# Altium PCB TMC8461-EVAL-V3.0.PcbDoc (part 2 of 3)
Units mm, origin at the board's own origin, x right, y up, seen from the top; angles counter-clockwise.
Board outline 79 x 85 mm, 4 copper layers (Top Layer, Mid1, Mid2, Bottom Layer), stack 1.572 mm thick; 182 components, 192 nets, 883 pads, 381 vias.
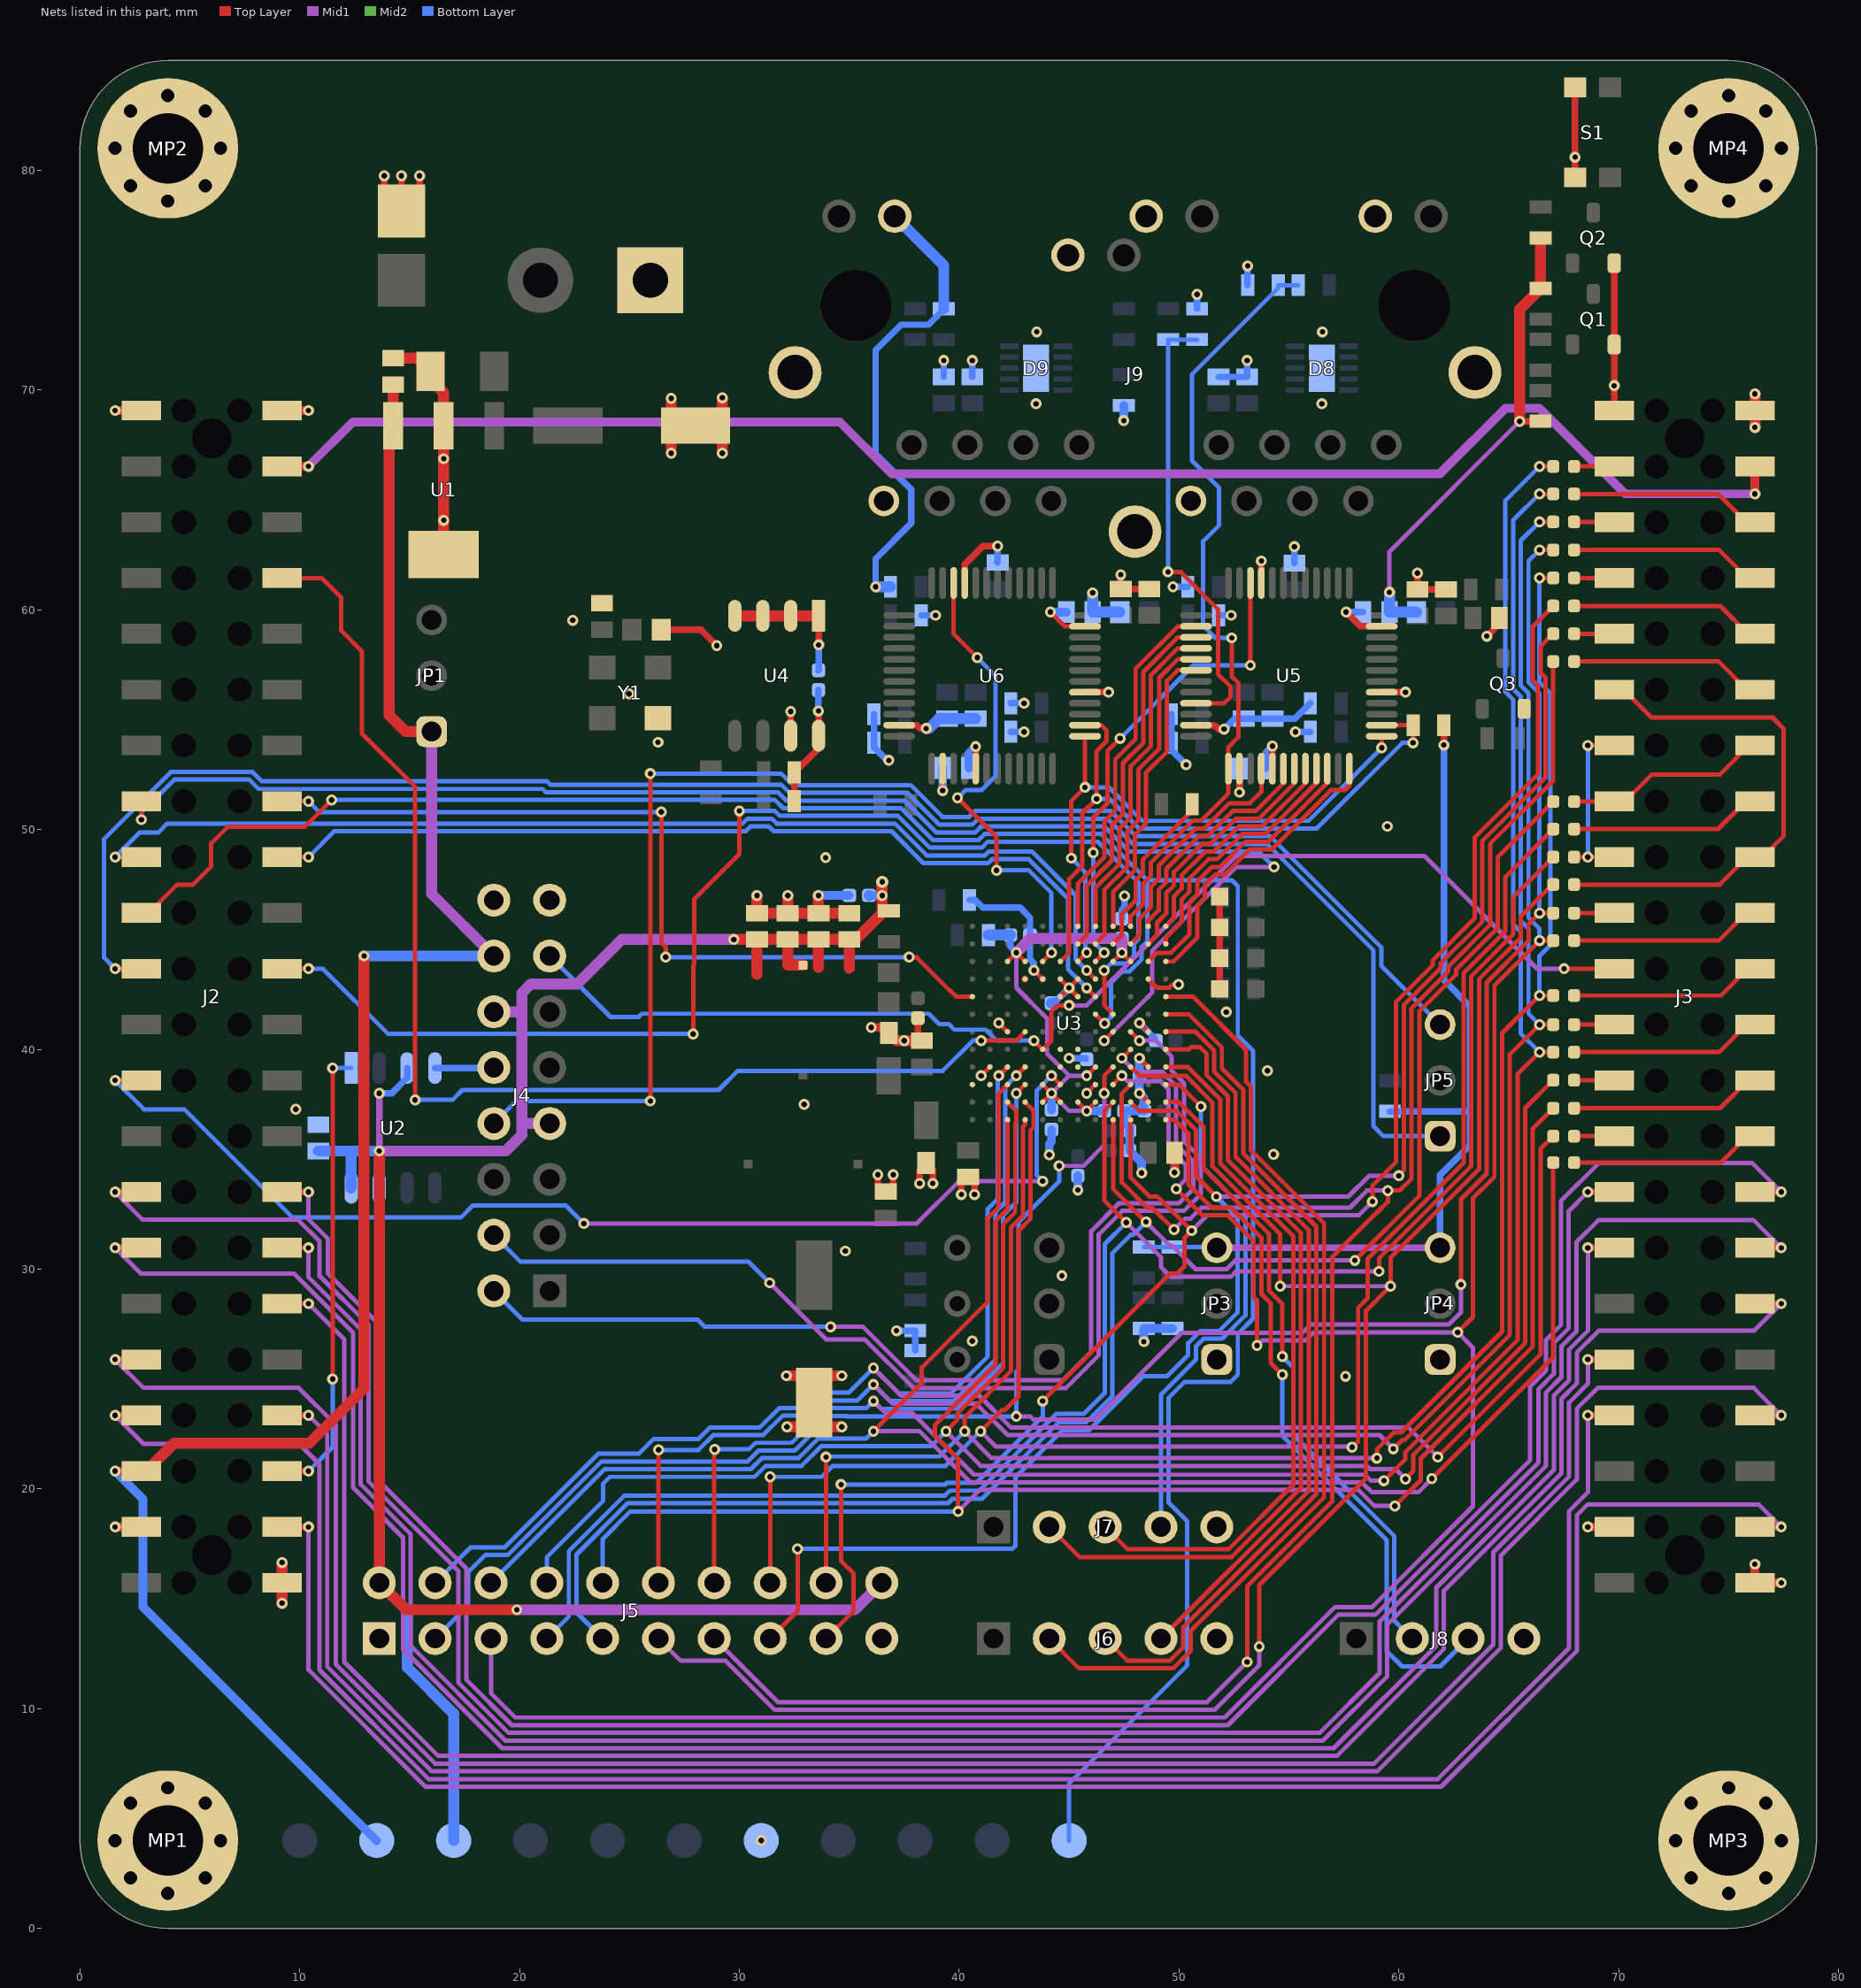
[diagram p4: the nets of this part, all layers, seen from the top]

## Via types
v1: diameter 0.5, hole 0.25, Top Layer to Bottom Layer, tented both sides, 379 vias
v2: diameter 0.5/0.5/0.5/0.5 (per signal layer), hole 0.25, Top Layer to Bottom Layer, tented both sides, 1 vias
v3: diameter 0.55, hole 0.25, Top Layer to Bottom Layer, tented both sides, 1 vias

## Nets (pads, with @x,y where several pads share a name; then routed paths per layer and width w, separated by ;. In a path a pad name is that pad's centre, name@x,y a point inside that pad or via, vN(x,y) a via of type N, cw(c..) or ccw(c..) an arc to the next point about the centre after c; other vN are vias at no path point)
+3V3: C4.2 C8.2 C9.2 C10.2 C11.2 C12.2 C24.2 C25.2 C26.2 C27.2 C30.2 C31.2 C32.2 C40.2 C41.2 J4.7 J4.12 J5.2 J5.20 J9.B11 JP3.3 JP4.3 L2.2 L4.2 L5.1 L6.1 R22.1 R28.2 R30.1 R32.2 R33.2 R40.2 R41.2 R44.2 R45.2 R46.2 R47.2 R49.1 R56.2 R60.1 R63.2 R67.2 TP3.1 U2.3 U2.7 U2.8 U3.C3 U3.D3 U3.E9 U3.E11 U3.F11 U3.G11 U3.H10 U3.H11 U3.J3 U3.K3 U4.8 U5.14 U6.14 | length 238.6
  Top Layer w0.2: v1(39.25,51.775) U6.14@39.25,52.775 ; U3.K3@42.2,44 v1(42.6,44.4) U3.J3@43,44 ; U3.H11@43.8,37.6 v1(44.2,38) ; U3.H10@43.8,38.4 v1(44.2,38) ; U3.G11@44.6,37.6 v1(44.2,38) ; U3.F11@45.4,37.6 v1(45.8,37.2) U3.E11@46.2,37.6 ; v1(45.8,38.8) U3.E9@46.2,39.2 ; U3.D3@47,44 v1(47.4,44.4) U3.C3@47.8,44
  Top Layer w0.3: L4.2@26.44,59.1 28.25,59.1 v1(28.975,58.375) ; R46.2@32.5,51.3 R45.2@32.5,52.6 33.605,53.705 U4.8@33.605,54.275 v1@33.605,55.4 ; v1@52.75,51.65 U5.14@52.75,52.775 ; v1(62.05,53.85) R44.2@62.05,54.75 ; v1@65.505,68.58 R30.1@66.445,68.58
  Top Layer w0.5: v1(13.62,35.375) J5.2@13.62,15.73 14.85,14.5 v1(19.875,14.5) ; v1(29.75,45) C11.2@30.8,45 ; 30.8,43.405 C11.2@30.8,45 ; L2.2@32.899,43.833 32.2,43.833 C10.2@32.2,45 ; 33.6,43.73 C9.2@33.6,45 ; 35,43.7 C8.2@35,45 ; v3(36.5,47.625) v1(36.5,47) 36.5,46.4 R22.1@36.6,46.3 ; R22.1@36.8,46.3 R22.1@36.6,46.3 ; v1(65.5,68.575) 65.5,73.675 R32.2@66.45,74.625 R33.2@66.45,76.925 ; C11.2@30.8,45 C10.2@32.2,45 ; C10.2@32.2,45 C9.2@33.6,45 ; C9.2@33.6,45 C8.2@35,45 ; C8.2@35,45 35.3,45 R22.1@36.6,46.3
  Mid1 w0.2: v1(42.6,44.4) 42.6,42.8 44,41.4 44,39.8 45,38.8 ; v1(45.8,37.2) 45,37.2 v1(44.2,38) 45,38.8 ; v1(45.8,38.8) 45,38.8 ; v1(59.575,60.8) 59.575,62.65 v1(65.5,68.575)
  Mid1 w0.3: v1(13.62,35.375) v1(13.62,38) ; JP3.3@51.72,30.97 JP4.3@61.88,30.97
  Mid1 w0.5: v1(13.62,35.375) 19.375,35.375 20.1,36.1 20.1,36.63 ; J4.12@18.83,41.71 20.06,41.71 ; v1(19.875,14.5) 35.25,14.5 J5.20@36.48,15.73 ; J4.7@21.37,36.63 20.1,36.63 ; v1(29.75,45) 24.65,45 22.625,42.975 20.525,42.975 20.1,42.55 20.1,36.63 ; v1(42.6,44.4) 43.25,45.05 47.4,45.05 v1(47.4,44.4)
  Mid2 w0.5: v1(36.5,47) v3(36.5,47.625)
  Bottom Layer w0.2: v1(47.4,44.4) C24.2@47.4,45.15 ; R41.2@48.4,31 R40.2@49.7,31 51.69,31 JP3.3@51.72,30.97
  Bottom Layer w0.3: v1(13.62,38) 14.187,38 14.885,38.698 U2.3@14.885,39.15 ; v1(33.6,55.4) C30.2@33.6,56.35 ; v1(36.2,61.05) 36.2,62.325 37.825,63.95 37.825,65.475 36.2,67.1 36.2,71.825 37.35,72.975 38.6,72.975 39.3,73.675 R63.2@39.3,73.7 ; C27.2@42.325,45.2 42.325,44.675 v1(42.6,44.4) ; R60.1@42.35,54.45 v1(42.95,54.45) ; v1(49.725,61.05) R56.2@50.4,61.05 ; v1(52.75,51.7) C31.2@52.75,52.775 ; v1(55.3,54.45) R49.1@55.975,54.45 ; R47.2@59.6,37.18 63.205,37.18 63.25,37.225 ; JP4.3@61.88,30.97 61.88,34.28 63.25,35.65 63.25,37.225 ; v1(62.05,53.85) 62.05,43.15 63.25,41.95 63.25,37.225
  Bottom Layer w0.4: C12.2@35.905,47 v1(36.5,47) ; v1(39.25,51.775) C40.2@39.25,52.8 ; C26.2@44.2,37.25 v1(44.2,38) ; v1(45.8,37.2) C25.2@46.6,37.2
  Bottom Layer w0.5: C4.2@10.85,35.375 12.35,35.375 ; U2.8@12.345,33.7 12.345,35.37 12.35,35.375 ; U2.7@13.615,33.7 13.62,33.705 v1(13.62,35.375) 12.35,35.375 ; J5.2@13.62,15.73 14.9,14.45 14.9,11.875 17,9.775 TP3.1@17,4 ; C12.2@35.9,47.005 C12.2@35.905,47 ; v1(36.2,61.05) R67.2@36.875,61.05 ; J9.B11@37.07,77.91 39.3,75.68 R63.2@39.3,73.7 ; R28.2@41.325,45.2 C27.2@42.325,45.2 ; v1(46.075,60.775) C41.2@46.075,59.9 L6.1@47.31,59.9 ; v1(59.575,60.8) C32.2@59.575,59.9 L5.1@60.81,59.9
+5V_REG: C3.2 J2.5 J4.14 JP1.1 TP2.1 U1.3 | length 88.9
  Top Layer w0.4: v1(1.6,20.81) J2.5@2.8,20.81
  Top Layer w0.5: J2.5@2.8,20.81 3.01,20.81 4.275,22.075 10.425,22.075 12.925,24.575 v1(12.925,44.25) ; C3.2@14.25,70.25 U1.3@14.25,68.375 14.075,68.2 14.075,55.2 14.815,54.46 JP1.1@16,54.46
  Mid1 w0.5: JP1.1@16,54.46 16,47.08 J4.14@18.83,44.25
  Bottom Layer w0.4: v1(1.6,20.81) 2.875,19.535 2.875,14.625 TP2.1@13.5,4
  Bottom Layer w0.5: v1(12.925,44.25) J4.14@18.83,44.25
+5V_VM: J2.42 J3.42 | length 72.9
  Top Layer w0.4: J2.42@9.2,66.53 v1(10.4,66.53) ; v1(76.2,65.275) J3.42@76.2,66.53
  Mid1 w0.4: v1(10.4,66.53) 12.42,68.55 34.575,68.55 36.925,66.2 61.875,66.2 64.85,69.175 66.4,69.175 70.3,65.275 v1(76.2,65.275)
\S\P\I\1\_\C\S\: J2.30 U3.M5 | length 38.8
  Top Layer w0.2: J2.30@9.2,51.29 v1(10.4,51.29) ; v1(26.45,50.8) 26.45,44.85 26.65,44.65 v1(26.65,44.2) ; v1(37.725,44.2) 38.073,44.2 38.083,44.19 38.083,44.167 39.594,42.657 39.616,42.657 39.873,42.4 U3.M5@40.6,42.4
  Bottom Layer w0.2: v1(10.4,51.29) 10.89,50.8 v1(26.45,50.8) ; v1(26.65,44.2) v1(37.725,44.2)
AIN0: J2.14 J3.14 | length 103.4
  Top Layer w0.2: J2.14@9.2,30.97 v1(10.4,30.97)
  Top Layer w0.3: J3.14@76.2,30.97 v1(77.4,30.97)
  Mid1 w0.2: v1(10.4,30.97) 10.4,29.632 12.775,27.257 12.775,20.205 15.05,17.93 15.05,12.855 19.355,8.55 56.55,8.55 59.475,11.475 59.475,13.825 66.7,21.05 66.7,24.39 67.4,25.09 67.4,26.49 68.075,27.165 68.075,31.225 69.075,32.225 76.145,32.225 v1(77.4,30.97)
AIN1: J2.15 J3.15 | length 105.1
  Top Layer w0.3: v1(1.6,33.51) J2.15@2.8,33.51 ; v1(68.6,33.51) J3.15@69.8,33.51
  Mid1 w0.2: v1(1.6,33.51) 2.86,32.25 9.925,32.25 10.9,31.275 10.9,29.7 13.125,27.475 13.125,20.35 17.225,16.25 17.225,11.175 19.5,8.9 56.405,8.9 59.125,11.62 59.125,13.97 66.35,21.195 66.35,24.535 67.05,25.235 67.05,26.635 67.725,27.31 67.725,32.635 v1(68.6,33.51)
AIN2: J2.16 J3.16 | length 105.5
  Top Layer w0.3: J2.16@9.2,33.51 v1(10.4,33.51) ; J3.16@76.2,33.51 v1(77.4,33.51)
  Mid1 w0.2: v1(10.4,33.51) 10.4,32.27 11.275,31.395 11.275,29.82 13.475,27.62 13.475,20.495 17.575,16.395 17.575,11.33 19.655,9.25 52.225,9.25 57.25,14.275 58.935,14.275 65.975,21.315 65.975,24.655 66.7,25.38 66.7,26.78 67.375,27.455 67.375,33.1 69.1,34.825 76.085,34.825 v1(77.4,33.51)
CLK_16MHZ_OUT: J3.23 J4.13 U3.H8 | length 56.9
  Top Layer w0.2: v1(43.4,40.4) U3.H8@43.8,40 44.2,40.4 44.2,41.73 44.47,42 v1(45,42) ; v1(67.52,43.67) J3.23@69.8,43.67
  Mid1 w0.2: v1(45,42) 45.8,42 52.6,48.8 61.165,48.8 66.295,43.67 v1(67.52,43.67)
  Bottom Layer w0.2: J4.13@21.37,44.25 24.145,41.475 25.408,41.475 25.558,41.625 38.618,41.625 39.093,41.15 39.525,41.15 39.775,40.9 41.207,40.9 41.5,40.607 41.5,40.6 41.7,40.4 v1(43.4,40.4)
CLK_25MHZ_OUT0: U3.E3 U5.46 | length 22.1
  Top Layer w0.2: v1(46.1,48.95) 46.1,50.55 46.45,50.9 46.457,50.9 46.75,51.193 46.75,53.575 v1(47.325,54.15) ; U3.E3@46.2,44 v1(46.6,44.4) ; v1(53.25,57.475) U5.46@53.25,61.225
  Bottom Layer w0.2: v1(46.1,48.95) 46.1,44.9 v1(46.6,44.4) ; v1(47.325,54.15) 50.65,57.475 v1(53.25,57.475)
CLK_25MHZ_OUT1: U3.H3 U6.46 | length 21.9
  Top Layer w0.2: U6.46@39.75,61.225 39.75,58.9 v1(40.825,57.825) ; v1(39.925,51.45) 41.675,49.7 ; v1(41.7,48.15) 41.7,49.675 ; U3.H3@43.8,44 v1(44.2,44.4)
  Bottom Layer w0.2: v1(39.925,51.45) 39.95,51.45 40.3,51.8 41.025,51.8 41.65,52.425 41.65,57 v1(40.825,57.825) ; v1(41.7,48.15) 43.17,48.15 44.2,47.12 v1(44.2,44.4)
CS_CH0: J2.6 U2.1 | length 20.8
  Top Layer w0.2: v1(11.5,25) v1(11.5,39.15)
  Top Layer w0.3: J2.6@9.2,20.81 v1(10.4,20.81)
  Bottom Layer w0.2: v1(10.4,20.81) 11.5,21.91 v1(11.5,25) ; v1(11.5,39.15) U2.1@12.345,39.15
DIO0: J2.8 J3.8 | length 94.4
  Top Layer w0.3: J2.8@9.2,23.35 v1(10.4,23.35) ; J3.8@76.2,23.35 v1(77.4,23.35)
  Mid1 w0.2: v1(10.4,23.35) 11.25,22.5 11.25,11.91 16.01,7.15 59.019,7.15 64.65,12.781 64.65,16.975 68.1,20.425 68.1,23.65 69.05,24.6 76.15,24.6 v1(77.4,23.35)
DIO1: J2.9 J3.9 | length 96.1
  Top Layer w0.3: v1(1.6,25.89) J2.9@2.8,25.89 ; v1(68.6,25.89) J3.9@69.8,25.89
  Mid1 w0.2: v1(1.6,25.89) 2.89,24.6 9.95,24.6 11.65,22.9 11.65,12.005 16.155,7.5 58.874,7.5 64.3,12.926 64.3,17.12 67.75,20.57 67.75,23.936 68.6,24.786 v1(68.6,25.89)
DIO4: J2.12 J3.12 | length 99.4
  Top Layer w0.2: J2.12@9.2,28.43 v1(10.4,28.43)
  Top Layer w0.3: J3.12@76.2,28.43 v1(77.4,28.43)
  Mid1 w0.2: v1(10.4,28.43) 12.025,26.805 12.025,12.125 16.3,7.85 57.179,7.85 62.05,12.721 62.05,15.365 67.4,20.715 67.4,24.1 68.1,24.8 68.1,26.2 69.1,27.2 76.17,27.2 v1(77.4,28.43)
DIO5: J2.13 J3.13 | length 101.9
  Top Layer w0.3: v1(1.6,30.97) J2.13@2.8,30.97 ; v1(68.6,30.97) J3.13@69.8,30.97
  Mid1 w0.2: v1(1.6,30.97) 2.77,29.8 9.737,29.8 12.425,27.112 12.425,20.06 14.7,17.785 14.7,12.71 19.21,8.2 57.034,8.2 61.7,12.866 61.7,15.51 67.05,20.86 67.05,24.245 67.75,24.945 67.75,26.345 68.6,27.195 v1(68.6,30.97)
DIO12: J3.34 R19.2 | length 8.7
  Top Layer w0.2: R19.2@68.075,57.65 74.55,57.65 75.83,56.37 J3.34@76.2,56.37
DIO13: J3.35 R20.2 | length 1.7
  Top Layer w0.2: R20.2@68.075,58.91 J3.35@69.8,58.91
DIO14: J3.36 R21.2 | length 8.3
  Top Layer w0.2: R21.2@68.075,60.175 74.625,60.175 J3.36@75.89,58.91
DIO15: J3.37 R16.2 | length 1.7
  Top Layer w0.2: R16.2@68.075,61.45 J3.37@69.8,61.45
DIO16: J3.38 R17.2 | length 8.7
  Top Layer w0.2: R17.2@68.075,62.725 74.575,62.725 75.85,61.45 J3.38@76.2,61.45
DIO17: J3.39 R18.2 | length 1.7
  Top Layer w0.2: R18.2@68.075,64 J3.39@69.79,64
DIO18: J3.40 R14.2 | length 8.7
  Top Layer w0.2: R14.2@68.075,65.275 74.525,65.275 75.81,63.99 J3.40@76.2,63.99
DIO19: J3.41 R15.2 | length 1.7
  Top Layer w0.2: R15.2@68.075,66.525 J3.41@69.795,66.525
EEPROM_OK: J2.38 U3.J7 | length 56.3
  Top Layer w0.2: J2.38@9.2,61.45 11,61.45 11.875,60.575 11.875,59.07 12.825,58.12 12.825,54.378 15.25,51.953 v1(15.25,37.7) ; v1(41,40.4) 42.6,40.4 U3.J7@43,40.8
  Bottom Layer w0.2: v1(15.25,37.7) 16.95,37.7 17.4,38.15 29.057,38.15 29.932,39.025 39.25,39.025 40.625,40.4 v1(41,40.4)
EN_16MHZ_OUT: J2.19 U3.G10 | length 53.1
  Top Layer w0.2: v1(1.6,38.59) J2.19@2.8,38.59 ; v1(44.2,38.8) U3.G10@44.6,38.4
  Mid1 w0.2: v1(22.925,32.075) 38.068,32.075 39.993,34 v1(43.8,34)
  Bottom Layer w0.2: v1(1.6,38.59) 2.915,37.275 4.75,37.275 9.675,32.35 17.325,32.35 17.875,32.9 22.1,32.9 v1(22.925,32.075) ; v1(43.8,34) 43.525,34.275 43.525,38.125 v1(44.2,38.8)
GND: C1.2 C2.1 C3.1 C4.1 C5.1 C6.1 C7.1 C8.1 C9.1 C10.1 C11.1 C12.1 C13.1 C14.1 C15.2 C16.1 C17.1 C18.1 C19.1 C20.1 C21.1 C22.1 C23.1 C24.1 C25.1 C26.1 C27.1 C28.1 C29.1 C30.1 C31.1 C32.1 C33.1 C34.1 C35.1 C36.1 C37.1 C38.1 C39.1 C40.1 C41.1 C42.1 C43.1 C44.1 C45.1 C46.1 C47.1 C48.1 D1.2 D2.2 D3.2 D4.1 D5.1 D6.1 D7.1 D8.11 D9.11 J1.1 J2.2 J2.3 J2.43 J2.44 J3.2 J3.3 J3.43 J3.44 J4.10 J4.15 J4.16 J5.1 J5.19 J6.5 J7.5 J8.4 J9.A8 J9.A10 J9.A12 J9.B8 J9.B10 J9.Shield JP3.1 JP4.1 MP1.1 MP2.1 MP3.1 MP4.1 Q1.2 Q2.2 Q3.2 R24.1 R26.1 R29.1 R42.1 R43.1 R50.1 R51.1 R52.1 R53.1 R54.1 R55.1 R61.1 R62.1 R64.1 R65.1 R66.1 S1.3 S1.4 TP7.1 U1.2 U1.4 U2.4 U3.B4 U3.B7 U3.B9 U3.B11 U3.E10 U3.F4 U3.F5 U3.F8 U3.F9 U3.G4 U3.G5 U3.G8 U3.G9 U3.H4 U3.J4 U3.K7 U3.L9 U3.L10 U3.M10 U4.1 U4.2 U4.3 U4.4 U4.7 U5.11 U5.17 U5.29 U5.35 U5.45 U6.11 U6.17 U6.29 U6.35 U6.45 Y1.2 | length 153
  Top Layer w0.2: v1(41,38.8) U3.L9@41.4,39.2 ; v1(41.8,41.2) U3.K7@42.2,40.8 ; v1(43.4,43.6) U3.H4@43.8,43.2 ; v1(44.15,59.9) 44.8,59.25 U6.35@45.725,59.25 ; U3.G5@44.6,42.4 v1(45,42.8) ; U3.G4@44.6,43.2 v1(45,42.8) ; U3.F5@45.4,42.4 v1(45,42.8) ; U3.F4@45.4,43.2 v1(45,42.8) ; v1(45.8,38) U3.E10@46.2,38.4 ; v1(48.2,38) U3.B11@48.6,37.6 ; v1(48.2,39.6) U3.B9@48.6,39.2 ; v1(48.2,41.2) U3.B7@48.6,40.8 ; U3.B4@48.6,43.2 49,42.8 49.55,42.8 49.7,42.95 v1(49.975,42.95)
  Top Layer w0.3: v1(13.85,79.75) 13.85,78.925 D1.2@14.625,78.15 ; v1(14.625,79.75) D1.2@14.625,78.15 ; v1(15.45,79.75) 15.45,78.975 D1.2@14.625,78.15 ; U4.7@32.335,54.275 v1(32.335,55.375) ; v1(33.605,58.405) U4.1@33.605,59.725 ; v1(36.3,34.3) 36.3,33.884 C14.1@36.658,33.526 37,33.868 v1(37,34.3) ; D2.2@36.55,41 D2.2@36.8,40.75 D2.2@37.15,40.4 ; U6.11@37.275,54.75 38.066,54.75 38.216,54.6 v1(38.5,54.6) ; C6.1@38.125,40.6 C13.1@38.125,41.425 ; v1(38.2,33.9) 38.2,34.525 D3.2@38.5,34.825 38.8,34.525 v1(38.8,33.9) ; C6.1@38.3,40.3 C6.1@38.3,40.4 ; v1(40.1,33.4) 40.1,33.9 C7.1@40.4,34.2 40.7,33.9 v1(40.7,33.4) ; U6.45@40.25,61.225 40.25,62.075 41.075,62.9 v1(41.75,62.9) ; U6.17@40.75,52.775 v1(40.75,53.775) ; U6.29@45.725,56.25 v1(46.8,56.25) ; v1(47.35,61.6) C44.1@47.35,60.95 C43.1@48.65,60.95 ; U5.11@50.775,54.75 51.572,54.75 51.622,54.7 51.675,54.7 51.8,54.575 v1(52.05,54.575) ; D7.1@51.85,42.75 D6.1@51.85,44.15 D5.1@51.85,45.55 D4.1@51.85,46.95 ; U5.45@53.75,61.225 v1(53.75,62.225) ; U5.17@54.25,52.775 v1(54.25,53.8) ; v1(57.6,59.9) 58.25,59.25 U5.35@59.225,59.25 ; U5.29@59.225,56.25 v1(60.3,56.25) ; v1(60.85,61.675) C34.1@60.85,60.925 C35.1@62.15,60.925 ; v1(64,58.8) 64.575,59.375 C29.1@64.575,59.625 ; S1.4@68.02,79.68 v1(68.02,80.6) S1.3@68.02,83.78 ; J3.43@69.8,69.07 Q1.2@69.8,72.075 Q2.2@69.8,75.775
  Top Layer w0.4: v1(1.6,18.27) J2.3@2.8,18.27 ; v1(1.6,69.07) J2.43@2.8,69.07 ; J2.44@9.2,69.07 v1(10.4,69.07) ; v1(36,41) D2.2@36.55,41 ; v1(49.8,34.4) C5.1@49.8,35.3 ; v1(68.6,18.27) J3.3@69.8,18.27 ; v1(76.2,16.575) J3.2@76.2,15.73 v1(77.4,15.73)
  Top Layer w0.5: v1(9.2,14.8) J2.2@9.2,15.73 v1(9.2,16.65) ; C3.1@14.25,71.45 15.35,71.45 C2.1@15.95,70.85 15.95,70.475 16.55,69.875 U1.2@16.55,68.375 v1(16.55,66.875) v1(16.55,64.075) U1.4@16.55,62.525 ; v1(26.9,67.125) v1(26.9,69.625) ; v1(29.225,67.125) v1(29.225,69.65) ; U4.4@29.795,59.725 U4.3@31.065,59.725 U4.2@32.335,59.725 U4.1@33.605,59.725 ; v1(30.8,47) C11.1@30.8,46.2 C10.1@32.2,46.2 ; v1(32.137,25.15) v1(34.662,25.15) ; v1(32.162,22.825) v1(34.662,22.825) ; v1(32.2,47) C10.1@32.2,46.2 ; v1(33.6,47) C9.1@33.6,46.2 ; C8.1@35,46.2 C9.1@33.6,46.2 ; D2.2@37.15,40.4 C6.1@38.3,40.4 ; v1(76.2,68.3) J3.44@76.2,69.07 v1(76.2,69.825) ; C10.1@32.2,46.2 C9.1@33.6,46.2
  Bottom Layer w0.2: C22.1@45.75,39.6 C22.1@45.8,39.55
  Bottom Layer w0.3: U2.4@16.155,39.15 18.81,39.15 J4.10@18.83,39.17 ; C30.1@33.6,57.25 33.605,57.255 v1(33.605,58.405) ; R64.1@36.125,55.25 R65.1@36.125,53.95 36.125,53.75 36.8,53.075 36.802,53.077 v1(36.802,53.153) ; v1(37.15,27.2) R26.1@38,27.2 R24.1@38,26.3 ; R61.1@38.275,59.75 v1(38.925,59.75) ; C48.1@39.3,70.6 v1(39.3,71.35) ; R29.1@40.475,46.8 40.722,46.8 41.072,46.45 42.775,46.45 43.225,46 C27.1@43.225,45.2 43.225,44.102 43.4,43.927 v1(43.4,43.6) ; C47.1@40.6,70.6 v1(40.6,71.35) ; C42.1@41.75,62.15 v1(41.75,62.9) ; R62.1@42.35,55.75 v1(42.95,55.75) ; C23.1@44.3,42.1 v1(45,42.8) ; v1(45,39.6) C22.1@45.75,39.6 ; C24.1@47.4,45.95 47.4,46.35 47.525,46.475 v1(47.525,46.975) ; v1(48.2,41.2) C20.1@48.9,40.5 ; R53.1@49.65,55.25 R54.1@49.65,53.95 49.65,53.625 v1(50.325,52.95) ; R52.1@50.825,73.7 v1(50.825,74.35) ; R50.1@51.8,59.75 v1(52.375,59.75) ; C38.1@51.8,70.6 C39.1@53.1,70.6 v1(53.1,71.35) ; v1(52.05,54.575) 52.525,55.05 C36.1@52.95,55.05 C37.1@54.25,55.05 55.275,55.05 R51.1@55.975,55.75 ; R55.1@53.125,74.775 v1(53.125,75.65) ; C31.1@53.95,52.775 53.95,53.5 v1(54.25,53.8) ; C33.1@55.25,62.125 v1(55.25,62.875) ; v1(57.6,59.9) C32.1@58.375,59.9
  Bottom Layer w0.4: v1@33.605,47.005 C12.1@35,47.005 ; C40.1@40.45,52.8 40.45,53.475 v1(40.75,53.775) ; v1(44.1,35.2) 44.1,35.7 44.2,35.8 C26.1@44.2,36.35 ; v1(44.15,59.9) C41.1@44.875,59.9 ; v1(45.4,33.6) C18.1@45.4,34.25 ; v1(47.49,68.61) R66.1@47.49,69.3 ; v1(48.2,39.6) C21.1@48.2,38.8 v1(48.2,38) 48.4,37.8 C19.1@48.4,37.2 ; v1(48.3,34.375) 48.3,34.85 C16.1@47.75,35.4 C17.1@47.75,36.3 47.75,36.45 47.5,36.7 C25.1@47.5,37.2 C19.1@48.4,37.2 ; v1(48.4,26.7) R43.1@48.4,27.3 R42.1@49.7,27.3 ; C19.1@48.425,37.2 C19.1@48.4,37.2
  Bottom Layer w0.5: v1(33.6,47) v1@33.605,47.005 ; v1(38.5,54.6) 38.625,54.6 39.075,55.05 C46.1@39.45,55.05 C45.1@40.75,55.05 ; C23.1@44.2,42.1 C23.1@44.3,42.1
  other v1: 31,4 57.575,25.125 40.6,26.725 44.675,29.7 34.825,30.825 54.3,35.225 9.825,37.275 32.95,37.5 54.025,39.025 37.5,40.4 52.15,41.7 33.925,48.725 59.475,50.15 26.3,53.975 24.975,56.175 22.425,59.525 43.5,69.375 56.5,69.375 69.8,70.2 43.525,72.65 56.525,72.65
ID_CH1: J2.7 J3.7 | length 94.3
  Top Layer w0.3: v1(1.6,23.35) J2.7@2.8,23.35 ; v1(68.6,23.35) J3.7@69.8,23.35
  Mid1 w0.2: v1(1.6,23.35) 2.9,22.05 9.975,22.05 10.9,21.125 10.9,11.765 15.865,6.8 61.78,6.8 67.75,12.77 67.75,19 68.6,19.85 v1(68.6,23.35)
IO_CLK: J2.4 J3.4 | length 87.5
  Top Layer w0.3: J2.4@9.2,18.27 v1(10.4,18.27) ; J3.4@76.2,18.27 v1(77.4,18.27)
  Mid1 w0.2: v1(10.4,18.27) 10.4,11.77 15.72,6.45 61.925,6.45 68.1,12.625 68.1,18.8 68.6,19.3 76.37,19.3 v1(77.4,18.27)
LATCH_IN0: J4.2 U3.C8 | length 48.9
  Top Layer w0.2: v1(47.4,39.6) U3.C8@47.8,40
  Mid1 w0.2: v1(34.15,27.375) 35.625,27.375 38.06,24.94 44.715,24.94 46,26.225 46,31.727 47.273,33 50,33 50.65,33.65 50.65,34.895 49.875,35.67 49.875,38.327 49.227,38.975 48.025,38.975 v1(47.4,39.6)
  Bottom Layer w0.2: J4.2@18.83,29.01 20.14,27.7 28.107,27.7 28.432,27.375 v1(34.15,27.375)
LATCH_IN1: J4.4 U3.C7 | length 51.1
  Top Layer w0.2: U3.C7@47.8,40.8 v1(48.2,40.4)
  Mid1 w0.2: v1(31.375,29.375) 33.95,26.8 35.705,26.8 37.915,24.59 44.86,24.59 46.35,26.08 46.35,31.582 47.418,32.65 50.225,32.65 51,33.425 51,35.04 50.225,35.815 50.225,38.472 49.674,39.024 49.674,39.676 48.95,40.4 v1(48.2,40.4)
  Bottom Layer w0.2: J4.4@18.83,31.55 20.03,30.35 30.4,30.35 v1(31.375,29.375)
M\F\C\_\E\S\_\H\E\A\D\E\R\: J4.8 JP5.3 | length 63.8
  Top Layer w0.2: v1(25.95,37.65) v1(25.95,52.55)
  Bottom Layer w0.2: J4.8@18.83,36.63 19.85,37.65 v1(25.95,37.65) ; v1(25.95,52.55) 31.9,52.55 32.425,52.025 37.795,52.025 39.245,50.575 40.448,50.575 40.723,50.85 46.89,50.85 48.04,49.7 54.15,49.7 59.2,44.65 59.2,43.81 JP5.3@61.88,41.13
M\F\C\_\E\S\_\M\C\U\: J2.23 JP5.1 | length 81.1
  Top Layer w0.2: v1(1.6,43.67) J2.23@2.8,43.67
  Bottom Layer w0.2: v1(1.6,43.67) 1.1,44.17 1.1,49.575 4.15,52.625 7.85,52.625 8.275,52.2 21.25,52.2 21.4,52.05 31.905,52.05 32.28,51.675 37.65,51.675 39.1,50.225 40.593,50.225 40.868,50.5 46.745,50.5 47.895,49.35 54,49.35 58.85,44.5 58.85,36.5 59.3,36.05 JP5.1@61.88,36.05
M\F\S\_\C\T\R\L\_\S\P\I\_\C\S\: J2.24 U3.D6 | length 57.9
  Top Layer w0.2: J2.24@9.2,43.67 v1(10.4,43.67) ; v1(27.9,40.7) 27.9,43.832 27.95,43.882 27.95,46.84 30,48.89 v1(30,50.85) ; v1(46.6,43.6) 46.6,42 U3.D6@47,41.6
  Bottom Layer w0.2: v1(10.4,43.67) 11.055,43.67 14.025,40.7 v1(27.9,40.7) ; v1(30,50.85) 31.62,50.85 31.845,50.625 37.215,50.625 38.665,49.175 41.028,49.175 41.303,49.45 46.307,49.45 48.15,47.607 48.15,45.01 47.955,44.815 47.955,44.248 47.607,43.9 46.9,43.9 v1(46.6,43.6)
MDC: U3.F3 U5.25 U6.25 | length 27
  Top Layer w0.2: v1(45.1,48.7) 45.1,51.3 v1(45.725,51.925) U6.25@45.725,54.25 ; U3.F3@45.4,44 v1(45.8,44.4) ; v1(59.225,53.725) U5.25@59.225,54.25
  Bottom Layer w0.2: v1(45.1,48.7) 45.75,48.05 45.75,44.45 v1(45.8,44.4) ; v1(45.725,51.925) 46.805,51.925 48.33,50.4 55.9,50.4 v1(59.225,53.725)
MDIO: R44.1 U3.G3 U5.26 U6.26 | length 31.3
  Top Layer w0.2: U3.G3@44.6,44 45,44.4 45,47.75 45.6,48.35 45.6,50.75 v1(46.25,51.4) 46.25,53.57 46.712,54.032 46.712,54.512 46.475,54.75 U6.26@45.725,54.75 ; U5.26@59.225,54.75 R44.1@60.65,54.75 v1(60.65,53.95)
  Bottom Layer w0.2: v1(46.25,51.4) 46.835,51.4 48.185,50.05 56.257,50.05 60.157,53.95 v1(60.65,53.95)
MFC_CTRL_SPI_MISO: J2.28 U3.E5 | length 42.8
  Top Layer w0.2: J2.28@9.2,48.75 v1(10.4,48.75) ; v1(45.8,42.8) U3.E5@46.2,42.4
  Bottom Layer w0.2: v1(10.4,48.75) 11.575,49.925 30.295,49.925 30.52,50.15 31.33,50.15 31.555,49.925 36.925,49.925 38.375,48.475 41.318,48.475 41.493,48.65 43.165,48.65 44.95,46.865 44.95,43.65 v1(45.8,42.8)
MFC_CTRL_SPI_MOSI: J2.29 U3.D7 | length 67.9
  Top Layer w0.2: v1(2.8,50.45) J2.29@2.8,51.29 ; v1(46.6,40.4) U3.D7@47,40.8
  Mid1 w0.2: v1(46.6,40.4) 48.775,42.575 48.775,44.48 52.595,48.3 v1(54.325,48.3)
  Bottom Layer w0.2: v1(2.8,50.45) 2.8,50.78 4.295,52.275 7.705,52.275 8.13,51.85 21.05,51.85 21.2,51.7 31.76,51.7 32.135,51.325 37.505,51.325 38.955,49.875 40.738,49.875 41.013,50.15 46.6,50.15 47.75,49 53.625,49 v1(54.325,48.3)
MFC_CTRL_SPI_SCK: J2.27 U3.E4 | length 51.4
  Top Layer w0.2: v1(1.6,48.75) J2.27@2.8,48.75 ; v1(45.8,43.6) U3.E4@46.2,43.2
  Bottom Layer w0.2: v1(1.6,48.75) 2.725,49.875 3.575,49.875 3.975,50.275 30.15,50.275 30.375,50.5 31.475,50.5 31.7,50.275 37.07,50.275 38.52,48.825 41.173,48.825 41.348,49 43.31,49 45.3,47.01 45.3,44.1 v1(45.8,43.6)
MFC_IRQ: J2.25 TP11.1 U3.E6 | length 111.7
  Top Layer w0.2: J2.25@2.8,46.21 3.135,46.21 4.425,47.5 5.15,47.5 5.975,48.325 5.975,49.375 6.725,50.125 10.225,50.125 v1(11.45,51.35) ; U3.E6@46.2,41.6 v1(46.619,41.181)
  Bottom Layer w0.2: v1(11.45,51.35) 31.615,51.35 31.99,50.975 37.36,50.975 38.81,49.525 40.883,49.525 41.158,49.8 46.452,49.8 48.562,47.69 48.562,44.927 48.305,44.67 48.305,44.103 47.752,43.55 47.443,43.55 46.9,43.007 46.9,42.593 ; TP11.1@45,4 45,6.6 50.375,11.975 50.375,18.525 49.53,19.37 49.53,24.15 50.255,24.875 52.35,24.875 52.675,25.2 52.675,27.052 53.37,27.747 53.37,39.93 52.675,40.625 52.675,47.429 52.404,47.7 48.562,47.7 ; v1(46.619,41.181) 46.9,41.462 46.9,42.593
MFC_PWM_HS_0_DIR: J3.18 R5.2 | length 8.7
  Top Layer w0.2: R5.2@67.975,34.85 74.65,34.85 75.85,36.05 J3.18@76.2,36.05
MFC_PWM_HS_1: J3.20 R3.2 | length 8.7
  Top Layer w0.2: R3.2@67.975,37.325 74.625,37.325 75.89,38.59 J3.20@76.2,38.59
MFC_PWM_HS_2: J3.22 R1.2 | length 8.7
  Top Layer w0.2: R1.2@67.975,39.875 74.575,39.875 75.83,41.13 J3.22@76.2,41.13
MFC_PWM_LS_0_STP: J3.17 R6.2 | length 1.8
  Top Layer w0.2: R6.2@67.975,36.05 J3.17@69.8,36.05
MFC_PWM_LS_1: J3.19 R4.2 | length 1.8
  Top Layer w0.2: R4.2@67.975,38.6 69.79,38.6 J3.19@69.8,38.59
MFC_PWM_LS_2: J3.21 R2.2 | length 1.8
  Top Layer w0.2: R2.2@67.975,41.125 69.795,41.125 J3.21@69.8,41.13
MFC_SPI_CS0: J3.30 R13.2 | length 8.7
  Top Layer w0.2: R13.2@67.975,50.025 74.525,50.025 75.79,51.29 J3.30@76.2,51.29
MFC_SPI_CS1: J3.24 R12.2 | length 8.7
  Top Layer w0.2: R12.2@67.975,42.45 74.65,42.45 75.87,43.67 J3.24@76.2,43.67
MFC_SPI_CS2: J3.25 R11.2 | length 1.8
  Top Layer w0.2: R11.2@67.975,46.2 69.79,46.2 J3.25@69.8,46.21
MFC_SPI_CS3: J3.26 R10.2 | length 8.7
  Top Layer w0.2: R10.2@67.975,44.95 74.55,44.95 75.81,46.21 J3.26@76.2,46.21
MFC_SPI_MISO: J3.28 J3.33 R7.2 | length 23.7
  Top Layer w0.2: R7.2@68.075,47.5 74.6,47.5 75.85,48.75 J3.28@76.2,48.75 76.55,48.75 77.5,49.7 77.5,54.6 77,55.1 71.5,55.1 70.23,56.37 J3.33@69.8,56.37
MFC_SPI_MOSI: J3.29 J3.32 R8.2 | length 9.3
  Top Layer w0.2: R8.2@67.975,51.275 69.785,51.275 J3.29@69.8,51.29 70.29,51.29 71.5,52.5 74.6,52.5 75.93,53.83 J3.32@76.2,53.83
MFC_SPI_SCK: J3.27 J3.31 R9.2 | length 8.1
  Top Layer w0.2: R9.2@67.975,48.75 v1(68.6,48.75) J3.27@69.8,48.75 ; v1(68.6,53.83) J3.31@69.8,53.83
  Bottom Layer w0.2: v1(68.6,48.75) v1(68.6,53.83)
MFCHVIO00: J6.2 U3.A5 | length 43.3
  Top Layer w0.2: J6.2@44.1,13.19 45.45,11.84 49.739,11.84 50.53,12.631 50.53,13.55 56.6,19.62 56.6,32.077 53.275,35.402 53.275,38.307 53.05,38.532 53.05,39.987 50.637,42.4 U3.A5@49.4,42.4
MFCHVIO01: J6.3 U3.A6 | length 39
  Top Layer w0.2: J6.3@46.64,13.19 47.64,12.19 49.594,12.19 50.18,12.776 50.18,13.695 56.25,19.765 56.25,31.932 52.925,35.257 52.925,38.162 51.95,39.137 51.95,40.097 50.447,41.6 U3.A6@49.4,41.6
MFCHVIO02: J6.4 U3.A7 | length 33.9
  Top Layer w0.2: J6.4@49.18,13.19 55.9,19.91 55.9,31.787 52.575,35.112 52.575,38.017 51.6,38.992 51.6,39.952 50.752,40.8 U3.A7@49.4,40.8
MFCHVIO03: J7.2 U3.A8 | length 36.9
  Top Layer w0.2: J7.2@44.1,18.27 45.47,16.9 52.395,16.9 55.55,20.055 55.55,31.642 52.225,34.967 52.225,37.872 51.25,38.847 51.25,39.807 50.957,40.1 50.543,40.1 50.443,40 U3.A8@49.4,40
MFCHVIO04: J7.3 U3.A9 | length 32.2
  Top Layer w0.2: J7.3@46.64,18.27 47.66,17.25 52.25,17.25 55.2,20.2 55.2,31.497 51.875,34.822 51.875,35.175 51.875,37.727 50.402,39.2 U3.A9@49.4,39.2
MFCHVIO05: J7.4 U3.A10 | length 24.1
  Top Layer w0.2: U3.A10@49.4,38.4 50,38.4 v1(51,37.4)
  Bottom Layer w0.2: J7.4@49.18,18.27 49.18,24.295 50.77,25.885 50.77,26.489 51.121,26.84 51.968,26.84 53.02,27.892 53.02,32.687 51,34.707 v1(51,37.4)
MFCHVIO06: J8.2 U3.A11 | length 29.4
  Top Layer w0.2: U3.A11@49.4,37.6 49.997,37.6 51.125,36.472 51.125,34.582 54.1,31.607 54.1,29.015 54.7,28.415 v1(54.7,26.025)
  Bottom Layer w0.2: v1(54.7,26.025) 55.2,25.525 55.2,22.45 59.8,17.85 59.8,14 J8.2@60.61,13.19
MFCHVIO07: J8.3 U3.A12 | length 33.6
  Top Layer w0.2: U3.A12@49.4,36.8 49.807,36.8 50.425,36.182 50.425,33.868 51.493,32.8 52.375,32.8 53.75,31.425 53.75,28.87 54.175,28.445 54.175,25.725 v1(54.7,25.2)
  Bottom Layer w0.2: v1(54.7,25.2) 54.7,22.425 59.45,17.675 59.45,12.625 60.15,11.925 61.885,11.925 J8.3@63.15,13.19
MFCIO00: J5.4 R6.1 U3.K9 | length 88
  Top Layer w0.2: v1(41.8,38.8) U3.K9@42.2,39.2 ; v1(61.775,21.45) 66.45,26.125 66.45,35.475 R6.1@67.025,36.05
  Mid1 w0.2: v1(36.1,25.5) 37.36,24.24 40.91,24.24 42.35,22.8 60.425,22.8 v1(61.775,21.45)
  Bottom Layer w0.2: J5.4@16.16,15.73 17.767,17.337 19.318,17.337 23.58,21.6 25.425,21.6 26.1,22.275 28.148,22.275 28.673,22.8 30.935,22.8 31.817,23.682 32.973,23.682 33.665,24.375 34.975,24.375 v1(36.1,25.5) 37.25,24.35 39.625,24.35 41.3,26.025 41.3,32.735 41.75,33.185 41.75,38.75 v1(41.8,38.8)
MFCIO01: J5.6 R5.1 U3.K10 | length 82
  Top Layer w0.2: v1(36.1,22.625) 38.3,24.825 38.3,25.525 41.3,28.525 41.3,32.33 41.8,32.83 41.8,38 U3.K10@42.2,38.4 ; v1(61.5,20.468) 67.025,25.993 R5.1@67.025,34.85
  Mid1 w0.2: v1(36.1,22.625) 38.198,22.625 40.523,20.3 58.31,20.3 58.585,20.025 58.6,20.025 58.775,19.85 60.882,19.85 v1(61.5,20.468)
  Bottom Layer w0.2: J5.6@18.7,15.73 23.87,20.9 30.525,20.9 31.025,21.4 32.688,21.4 33.588,22.3 35.775,22.3 v1(36.1,22.625)
MFCIO02: J5.8 R4.1 U3.K11 | length 81.4
  Top Layer w0.2: v1(39.4,22.625) 39.9,23.125 39.9,23.405 42,25.505 42,32.04 42.55,32.59 42.55,36.62 42.6,36.67 42.6,37.2 U3.K11@42.2,37.6 ; v1(60.3,20.45) 60.65,20.8 60.65,21.53 65.75,26.63 65.75,37.325 R4.1@67.025,38.6
  Mid1 w0.2: v1(39.4,22.625) 40.975,21.05 58.55,21.05 58.7,20.9 59.85,20.9 v1(60.3,20.45)
  Bottom Layer w0.2: J5.8@21.24,15.73 21.24,16.89 23.793,19.443 23.793,20.225 24.118,20.55 30.693,20.55 31.193,21.05 32.833,21.05 33.733,21.95 38.725,21.95 v1(39.4,22.625)
MFCIO03: J5.10 R3.1 U3.K12 | length 80
  Top Layer w0.2: v1(39.95,18.975) 39.95,21.368 38.9,22.418 38.9,22.9 41.65,25.65 41.65,32.185 42.2,32.735 U3.K12@42.2,36.8 ; v1(59.825,19.225) 61,20.4 61,21.385 66.1,26.485 66.1,36.4 R3.1@67.025,37.325
  Mid1 w0.2: v1(39.95,18.975) 40.925,19.95 58.165,19.95 58.89,19.225 v1(59.825,19.225)
  Bottom Layer w0.2: J5.10@23.78,15.73 23.78,17.715 25.04,18.975 v1(39.95,18.975)
MFCIO04: J5.12 R2.1 R14.1 U3.J9 | length 110.9
  Top Layer w0.2: J5.12@26.32,15.73 v1@26.32,21.775 ; v1(42.6,38.8) U3.J9@43,39.2 ; v1(59.75,21.825) 60.15,22.225 60.259,22.225 65.05,27.016 65.05,39.775 v1(66.4,41.125) R2.1@67.025,41.125 ; v1(66.4,65.275) R14.1@67.025,65.275
  Mid1 w0.2: v1(36.1,24.75) 36.96,23.89 40.765,23.89 42.205,22.45 59.125,22.45 v1(59.75,21.825)
  Bottom Layer w0.2: v1(26.325,21.775) 28.143,21.775 28.818,22.45 31.08,22.45 31.962,23.332 33.118,23.332 33.81,24.025 35.375,24.025 v1(36.1,24.75) 36.85,24 39.775,24 41.65,25.875 41.65,32.59 42.1,33.04 42.1,38.3 v1(42.6,38.8) ; v1(66.4,41.125) 65.9,41.625 65.9,45.498 65.55,45.848 65.55,56.06 65.2,56.41 65.2,64.075 v1(66.4,65.275)
MFCIO05: J5.14 R1.1 R15.1 U3.J10 | length 110.5
  Top Layer w0.2: J5.14@28.86,15.73 v1@28.86,21.8 ; v1(42.6,38) U3.J10@43,38.4 ; v1(59.325,20.375) 60.3,21.35 60.3,21.675 65.4,26.775 65.4,35.575 65.4,38.875 v1(66.4,39.875) R1.1@67.025,39.875 ; v1(66.4,66.525) R15.1@67.025,66.525
  Mid1 w0.2: v1(36.1,24) 36.65,23.45 37.868,23.45 40.668,20.65 58.455,20.65 58.73,20.375 v1(59.325,20.375)
  Bottom Layer w0.2: v1(28.875,21.8) 30.435,21.8 30.735,22.1 32.38,22.1 33.955,23.675 35.775,23.675 v1(36.1,24) 36.45,23.65 39.92,23.65 42,25.73 42,32.445 42.6,33.045 v1(42.6,38) ; v1(66.4,39.875) 65.55,40.725 65.55,45.353 65.2,45.703 65.2,55.915 64.85,56.265 64.85,64.975 v1(66.4,66.525)
MFCIO06: J5.16 R13.1 U3.J11 | length 80.6
  Top Layer w0.2: J5.16@31.4,15.73 v1(31.4,20.55) ; v1(40.975,22.625) 41.925,23.575 42.057,23.575 42.7,24.218 42.7,31.75 43.25,32.3 43.25,36.33 43.375,36.455 43.375,37.225 U3.J11@43,37.6 ; v1@57.875,22 58,22 58.15,22.15 58.15,28.245 58.575,28.67 58.575,30.465 62.95,34.84 62.95,43.235 62.95,43.48 64.85,45.38 64.85,47.85 R13.1@67.025,50.025
  Mid1 w0.2: v1(40.975,22.625) 41.675,21.925 57.8,21.925 v1@57.875,22
  Bottom Layer w0.2: v1(31.4,20.55) 33.747,20.55 34.247,21.05 39.382,21.05 40.957,22.625 v1(40.975,22.625)
  other v1: 57.875,21.9
MFCIO07: J5.18 R12.1 R16.1 U3.J12 | length 92.1
  Top Layer w0.2: J5.18@33.94,15.73 33.94,18.975 ; 33.946,18.975 v1@33.95,21.45 ; v1(40.25,22.625) 40.25,23.26 42.35,25.36 42.35,31.895 42.9,32.445 42.9,36.475 43,36.575 U3.J12@43,36.8 ; v1@59,21.375 v1(59,21.4) 59,21.8 59.775,22.575 60.114,22.575 64.7,27.161 64.7,40.75 v1(66.4,42.45) R12.1@67.025,42.45 ; v1(66.4,61.45) R16.1@67.025,61.45
  Mid1 w0.2: v1(40.25,22.625) 41.475,21.4 v1(59,21.4)
  Bottom Layer w0.2: v1(33.94,21.45) 33.965,21.475 39.1,21.475 v1(40.25,22.625) ; v1(66.4,42.45) 66.4,44.25 66.6,44.45 66.607,44.45 66.9,44.743 66.9,56.2 66.4,56.7 v1(66.4,61.45)
MFCIO08: J5.3 R11.1 R17.1 U3.D9 | length 110.1
  Top Layer w0.2: v1(46.6,38) 46.6,38.8 U3.D9@47,39.2 ; v1@62.83,29.3 62.83,33.18 64,34.35 64,42.8 64,43.045 65.9,44.945 65.9,45.7 v1(66.4,46.2) R11.1@67.025,46.2 ; v1(66.4,62.725) R17.1@67.025,62.725
  Mid1 w0.2: v1(42.6,23.3) 43.23,23.3 43.38,23.15 46.17,23.15 50.12,27.1 55.62,27.1 55.995,27.475 62.269,27.475 62.83,28.036 62.83,29.295 v1(62.825,29.3) ; v1(44.55,34.7) 45.657,34.7 46.6,35.643 v1(46.6,38)
  Bottom Layer w0.2: J5.3@16.16,13.19 17.655,14.685 17.655,16.205 18.437,16.987 19.463,16.987 23.725,21.25 30.38,21.25 30.88,21.75 32.525,21.75 34.1,23.325 34.869,23.325 34.893,23.3 42.55,23.3 v1@42.6,23.35 ; v1(42.6,23.3) v1@42.6,23.35 ; v1(44.55,34.7) 44.55,34 42.7,32.15 42.7,25.44 42.6,25.34 v1@42.6,23.35 ; v1(66.4,46.2) 66.4,56.2 65.9,56.7 65.9,62.225 v1(66.4,62.725)
MFCIO09: J5.5 R10.1 R18.1 U3.D10 | length 126.8
  Top Layer w0.2: U3.D10@47,38.4 v1(47.4,38.8) ; v1(49.875,33.65) 51.075,32.45 52.225,32.45 53.4,31.275 53.4,28.725 53.55,28.575 v1(53.55,26.525) ; v1(62.675,27.125) 63.375,27.825 63.375,33.225 64.35,34.2 64.35,42.9 v1(66.4,44.95) R10.1@67.025,44.95 ; v1(66.4,64) R18.1@67.025,64
  Mid1 w0.2: J5.5@18.7,13.19 18.7,10.7 19.8,9.6 52.08,9.6 57.105,14.625 58.79,14.625 63.375,19.21 63.375,26.425 v1(62.675,27.125) 56.14,27.125 55.765,26.75 53.775,26.75 v1(53.55,26.525) ; v1(47.4,38.8) 47.65,38.55 49.157,38.55 49.525,38.182 49.525,35.525 50.3,34.75 50.3,34.075 v1(49.875,33.65)
  Bottom Layer w0.2: v1(66.4,44.95) 66.4,45.493 65.9,45.993 65.9,56.205 65.55,56.555 65.55,63.15 v1(66.4,64)
MFCIO10: J5.7 R9.1 U3.D11 | length 81
  Top Layer w0.2: U3.D11@47,37.6 46.6,37.2 46.6,33.125 v1(47.6,32.125) ; v1(59.1,29.9) 59.1,30.495 63.3,34.695 63.3,43.09 63.3,43.335 65.2,45.235 65.2,46.925 R9.1@67.025,48.75
  Mid1 w0.2: v1(47.6,32.125) 49.175,30.55 49.175,30.1 49.625,29.65 52.35,29.65 52.6,29.9 v1(59.1,29.9)
  Bottom Layer w0.2: J5.7@21.24,13.19 22.24,14.19 22.24,17.165 24.775,19.7 39.355,19.7 39.58,19.925 40.922,19.925 44.41,23.412 45.662,23.412 46.625,24.375 46.625,31.15 v1(47.6,32.125)
MFCIO11: J5.9 R8.1 U3.D12 | length 80.7
  Top Layer w0.2: U3.D12@47,36.8 47,33.65 v1(48.5,32.15) ; v1(58,30.4) 60.93,33.33 60.93,41.729 62.6,43.399 62.6,43.625 64.5,45.525 64.5,48.75 R8.1@67.025,51.275
  Mid1 w0.2: v1(48.5,32.15) 49.575,31.075 49.675,31.075 50.75,30 52.175,30 52.575,30.4 v1(58,30.4)
  Bottom Layer w0.2: J5.9@23.78,13.19 22.59,14.38 22.59,17.02 24.92,19.35 39.5,19.35 39.7,19.55 41.042,19.55 44.517,23.025 45.77,23.025 46.975,24.23 46.975,30.729 47.811,31.564 47.914,31.564 v1(48.5,32.15)
MFCIO12: J5.11 R7.1 U3.C9 | length 89.6
  Top Layer w0.2: U3.C9@47.8,39.2 48.2,38.8 50.307,38.8 51.525,37.582 51.525,34.677 54.6,31.602 v1(54.6,29.225) ; v1(53.65,12.825) 53.65,15.625 58.5,20.475 58.5,28.1 v1(59.625,29.225) 59.625,30.525 63.65,34.55 63.65,42.945 63.65,43.19 65.55,45.09 65.55,46.057 66.993,47.5 R7.1@67.025,47.5
  Mid1 w0.2: J5.11@26.32,13.19 27.332,12.178 29.378,12.178 31.605,9.95 51.632,9.95 53.65,11.968 v1(53.65,12.825) ; v1(54.6,29.225) v1(59.625,29.225)
MFCIO13: J5.13 R19.1 U3.C10 | length 96.1
  Top Layer w0.2: U3.C10@47.8,38.4 47.4,38 47.4,33.95 48.55,32.8 48.775,32.8 v1(49.775,31.8) ; v1(53.1,12.125) 53.1,15.57 56.975,19.445 56.975,30.55 59,32.575 59.007,32.575 59.5,33.068 v1(59.5,33.575) 60.032,33.575 60.58,34.123 60.58,41.874 62.25,43.544 62.25,43.77 64.15,45.67 64.15,49.35 67.025,52.225 R19.1@67.025,57.65
  Mid1 w0.2: J5.13@28.86,13.19 31.75,10.3 51.275,10.3 v1(53.1,12.125) ; v1(49.775,31.8) 50.275,32.3 50.525,32.3 51.025,32.8 57.775,32.8 58.55,33.575 v1(59.5,33.575)
MFCIO14: J5.15 R20.1 U3.C11 | length 80.2
  Top Layer w0.2: J5.15@31.4,13.19 32.65,14.44 v1(32.65,17.27) ; U3.C11@47.8,37.6 48.2,37.2 49.902,37.2 50.775,36.327 50.775,34.225 v1(51.7,33.3) ; v1(60,34.25) 60.23,34.48 60.23,42.018 61.9,43.688 61.9,43.915 63.8,45.815 63.8,49.495 66.675,52.37 66.675,56.925 66.45,57.15 66.45,58.335 R20.1@67.025,58.91
  Mid1 w0.2: v1(51.7,33.3) 57.7,33.3 58.65,34.25 v1(60,34.25)
  Bottom Layer w0.2: v1(32.65,17.27) 42.414,17.27 42.56,17.416 42.56,20.535 44.7,22.675 45.915,22.675 48.377,25.138 49.463,25.138 50.42,26.095 50.42,26.634 50.976,27.19 51.824,27.19 52.67,28.036 52.67,32.33 v1(51.7,33.3)
MFCIO15: J5.17 R21.1 U3.C12 | length 75.6
  Top Layer w0.2: J5.17@33.94,13.19 35.2,14.45 35.2,16.15 34.625,16.725 v1(34.625,20.2) ; v1(43.8,24) 49.6,29.8 49.925,29.8 50.25,30.125 50.25,31.425 v2(50.575,31.75) 49.016,33.309 48.659,33.309 47.8,34.168 U3.C12@47.8,36.8 ; v1(58.8,33.075) 58.8,33.8 59.88,34.88 59.88,42.163 61.55,43.833 61.55,44.06 63.45,45.96 63.45,49.64 66.325,52.515 66.325,56.575 66.1,56.8 66.1,59.25 R21.1@67.025,60.175
  Mid1 w0.2: v2(50.575,31.75) 51.275,32.45 58.175,32.45 v1(58.8,33.075)
  Bottom Layer w0.2: v1(34.625,20.2) 39.36,20.2 39.435,20.275 40.777,20.275 43.8,23.298 v1(43.8,24)
MII1_LED_ACT: R52.2 R58.1 U5.9 | length 20.8
  Top Layer w0.2: v1(49.5,61.725) 50.075,61.725 51.775,60.025 51.775,57.075 52.35,56.5 52.35,56.043 52.057,55.75 U5.9@50.775,55.75
  Bottom Layer w0.2: v1(49.5,61.725) R58.1@49.5,72.3 R52.2@50.825,72.3
MII1_LINK: R55.2 R57.1 U3.C1 U5.13 | length 35.9
  Top Layer w0.2: U3.C1@47.8,45.6 47.8,46.048 48.375,46.623 48.375,47.548 48.725,47.898 48.725,48.505 50.62,50.4 51.004,50.4 52.25,51.646 U5.13@52.25,52.775 52.25,53.75 52.7,54.2 52.7,56.675 52.4,56.975 v1(52.4,58.725)
  Bottom Layer w0.2: v1(52.4,58.725) 51.65,58.725 51.1,59.275 51.1,63.125 51.825,63.85 51.825,65.55 50.6,66.775 50.6,70.725 54.525,74.65 R55.2@54.525,74.775 R57.1@55.425,74.775
MII1_RX_CLK: U3.C2 U5.16 | length 11.2
  Top Layer w0.2: U3.C2@47.8,44.8 48.2,45.2 48.2,45.953 48.725,46.478 48.725,47.403 49.075,47.753 49.075,48.36 50.765,50.05 51.149,50.05 52.299,51.2 53.225,51.2 53.75,51.725 U5.16@53.75,52.775
MII1_RX_DV: U3.B3 U5.22 | length 13.4
  Top Layer w0.2: U3.B3@48.6,44 49,44.4 49.64,44.4 50.475,45.235 50.475,46.678 50.825,47.028 50.825,47.635 51.49,48.3 51.873,48.3 53.023,49.45 54.073,49.45 56.75,52.127 U5.22@56.75,52.775
MII1_RX_ER: U3.A3 U5.24 | length 13.6
  Top Layer w0.2: U3.A3@49.4,44 49.75,44 50.825,45.075 50.825,46.533 51.175,46.883 51.175,47.49 51.635,47.95 52.075,47.95 53.225,49.1 54.218,49.1 56.918,51.8 57.55,51.8 57.75,52 U5.24@57.75,52.775
MII1_RXD0: U3.A2 U5.21 | length 11.7
  Top Layer w0.2: U3.A2@49.4,44.8 49.4,45.07 50.125,45.795 50.125,46.823 50.475,47.173 50.475,47.78 51.345,48.65 51.728,48.65 52.878,49.8 53.928,49.8 56.25,52.122 U5.21@56.25,52.775
MII1_RXD1: U3.A1 U5.20 | length 10.6
  Top Layer w0.2: U3.A1@49.4,45.6 49.775,45.975 49.775,46.968 50.125,47.318 50.125,47.925 51.2,49 51.583,49 52.733,50.15 53.783,50.15 55.75,52.117 U5.20@55.75,52.775
MII1_RXD2: U3.B2 U5.19 | length 11.6
  Top Layer w0.2: U3.B2@48.6,44.8 49,45.2 49,45.763 49.425,46.188 49.425,47.113 49.775,47.463 49.775,48.07 51.055,49.35 51.438,49.35 52.588,50.5 53.638,50.5 55.25,52.112 U5.19@55.25,52.775
MII1_RXD3: U3.B1 U5.18 | length 10.6
  Top Layer w0.2: U3.B1@48.6,45.6 48.6,45.858 49.075,46.333 49.075,47.258 49.425,47.608 49.425,48.215 50.91,49.7 51.293,49.7 52.443,50.85 53.493,50.85 54.75,52.107 U5.18@54.75,52.775
MII1_TX_CLK: R48.1 U3.D2 | length 7.9
  Top Layer w0.2: U3.D2@47,44.8 47.4,45.2 47.4,46.143 48.025,46.768 48.025,47.693 48.35,48.018 48.35,48.625 50.7,50.975 R48.1@50.7,51.15
MII1_TX_EN: U3.F1 U5.2 | length 16.4
  Top Layer w0.2: U3.F1@45.4,45.6 45.4,47.543 46.6,48.743 46.6,50.355 47.1,50.855 47.1,53.2 48.025,54.125 48.025,57.322 49.953,59.25 U5.2@50.775,59.25
MII1_TXD0: U3.D1 U5.6 | length 13.7
  Top Layer w0.2: U3.D1@47,45.6 47,47.163 48,48.163 48,49.775 48.5,50.275 48.5,52.59 49.45,53.54 49.45,56.767 49.933,57.25 U5.6@50.775,57.25
MII1_TXD1: U3.E2 U5.5 | length 15.3
  Top Layer w0.2: U3.E2@46.2,44.8 46.6,45.2 46.6,47.258 47.65,48.308 47.65,49.92 48.15,50.42 48.15,52.735 49.1,53.685 49.1,56.912 49.938,57.75 U5.5@50.775,57.75
MII1_TXD2: U3.E1 U5.4 | length 15
  Top Layer w0.2: U3.E1@46.2,45.6 46.2,47.353 47.3,48.453 47.3,50.065 47.8,50.565 47.8,52.88 48.725,53.805 48.725,57.032 49.943,58.25 U5.4@50.775,58.25
MII1_TXD3: U3.F2 U5.3 | length 16.7
  Top Layer w0.2: U3.F2@45.4,44.8 45.8,45.2 45.8,47.448 46.95,48.598 46.95,50.21 47.45,50.71 47.45,53.025 48.375,53.95 48.375,57.177 49.948,58.75 U5.3@50.775,58.75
